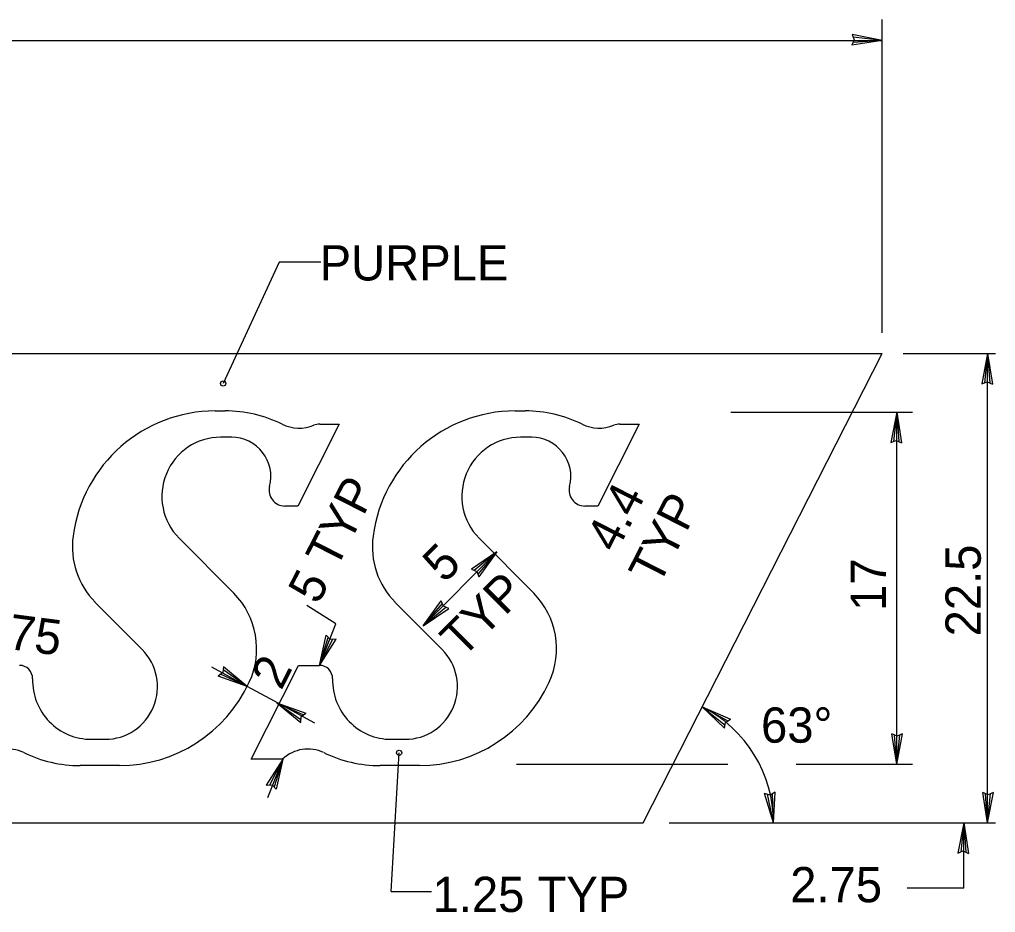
# Model space of a CAD drawing. Extents: x 10268197 to 10269179, y 2141503 to 2142677.
# Drawn here: x 10268496.62 to 10268515.98, y 2142153.63 to 2142171.35 of the extents above; entities that cross this region are included whole.
import ezdxf

# ---------------------------------------------------------------- set-up
doc = ezdxf.new("R2010")
doc.units = 0
for name, color, linetype in [('1', 7, 'Continuous'), ('2', 7, 'Continuous'), ('21', 7, 'Continuous')]:
    doc.layers.add(name, color=color, linetype=linetype)

msp = doc.modelspace()

# ---------------------------------------------------------------- linework, layer by layer
at = {"layer": '1'}
for p, q in [((10268513.738, 2142165.135), (10268513.738, 2142171.353)), ((10268491.278, 2142170.939), (10268513.738, 2142170.939)), ((10268513.181, 2142170.949), (10268513.133, 2142170.843)), ((10268513.738, 2142170.939), (10268513.133, 2142170.843)), ((10268513.738, 2142170.939), (10268513.137, 2142171.056)), ((10268513.137, 2142171.056), (10268513.181, 2142170.949)), ((10268513.738, 2142170.939), (10268513.159, 2142170.899)), ((10268513.738, 2142170.939), (10268513.16, 2142171)), ((10268501.773, 2142166.536), (10268500.658, 2142164.128)), ((10268502.595, 2142166.536), (10268501.773, 2142166.536)), ((10268514.152, 2142164.721), (10268515.983, 2142164.721)), ((10268515.827, 2142164.721), (10268515.71, 2142164.119)), ((10268515.827, 2142164.721), (10268515.767, 2142164.142)), ((10268515.827, 2142155.405), (10268515.827, 2142164.721)), ((10268515.827, 2142164.721), (10268515.923, 2142164.115)), ((10268515.827, 2142164.721), (10268515.868, 2142164.142)), ((10268515.71, 2142164.119), (10268515.817, 2142164.164)), ((10268515.817, 2142164.164), (10268515.923, 2142164.115)), ((10268510.735, 2142163.557), (10268514.337, 2142163.557)), ((10268514.023, 2142163.557), (10268513.907, 2142162.955)), ((10268514.023, 2142163.557), (10268513.963, 2142162.978)), ((10268514.023, 2142156.569), (10268514.023, 2142163.557)), ((10268514.023, 2142163.557), (10268514.119, 2142162.951)), ((10268514.023, 2142163.557), (10268514.064, 2142162.977)), ((10268513.907, 2142162.955), (10268514.014, 2142162.999)), ((10268514.014, 2142162.999), (10268514.119, 2142162.951)), ((10268504.628, 2142159.32), (10268506.092, 2142160.784)), ((10268506.092, 2142160.784), (10268505.584, 2142160.44)), ((10268506.092, 2142160.784), (10268505.64, 2142160.417)), ((10268506.092, 2142160.784), (10268505.711, 2142160.345)), ((10268506.092, 2142160.784), (10268505.732, 2142160.288)), ((10268505.584, 2142160.44), (10268505.691, 2142160.396)), ((10268505.691, 2142160.396), (10268505.732, 2142160.288)), ((10268502.894, 2142159.357), (10268502.319, 2142159.723)), ((10268504.628, 2142159.32), (10268504.988, 2142159.816)), ((10268504.628, 2142159.32), (10268505.01, 2142159.758)), ((10268504.628, 2142159.32), (10268505.08, 2142159.686)), ((10268505.029, 2142159.707), (10268504.988, 2142159.816)), ((10268505.137, 2142159.663), (10268505.029, 2142159.707)), ((10268504.628, 2142159.32), (10268505.137, 2142159.663)), ((10268502.571, 2142158.533), (10268502.894, 2142159.357)), ((10268502.571, 2142158.533), (10268502.703, 2142159.131)), ((10268502.783, 2142159.048), (10268502.703, 2142159.131)), ((10268502.571, 2142158.533), (10268502.744, 2142159.087)), ((10268502.571, 2142158.533), (10268502.899, 2142159.05)), ((10268502.571, 2142158.533), (10268502.838, 2142159.05)), ((10268502.899, 2142159.05), (10268502.783, 2142159.048)), ((10268501.138, 2142158.113), (10268500.438, 2142158.495)), ((10268501.592, 2142157.866), (10268501.138, 2142158.113)), ((10268502.479, 2142157.383), (10268501.592, 2142157.866)), ((10268510.166, 2142157.711), (10268510.726, 2142157.462)), ((10268510.166, 2142157.711), (10268510.608, 2142157.285)), ((10268510.166, 2142157.711), (10268510.618, 2142157.345)), ((10268510.166, 2142157.711), (10268510.674, 2142157.429)), ((10268510.608, 2142157.285), (10268510.628, 2142157.399)), ((10268510.628, 2142157.399), (10268510.726, 2142157.462)), ((10268514.023, 2142156.569), (10268513.927, 2142157.175)), ((10268514.033, 2142157.127), (10268513.927, 2142157.175)), ((10268514.023, 2142156.569), (10268514.14, 2142157.171)), ((10268514.14, 2142157.171), (10268514.033, 2142157.127)), ((10268514.023, 2142156.569), (10268513.983, 2142157.149)), ((10268514.023, 2142156.569), (10268514.084, 2142157.148)), ((10268503.991, 2142154.044), (10268504.15, 2142156.797)), ((10268501.844, 2142156.674), (10268501.516, 2142156.157)), ((10268501.844, 2142156.674), (10268501.541, 2142155.903)), ((10268501.844, 2142156.674), (10268501.577, 2142156.158)), ((10268501.844, 2142156.674), (10268501.67, 2142156.12)), ((10268501.844, 2142156.674), (10268501.713, 2142156.075)), ((10268506.478, 2142156.569), (10268510.674, 2142156.569)), ((10268512.027, 2142156.569), (10268514.337, 2142156.569)), ((10268501.516, 2142156.157), (10268501.632, 2142156.159)), ((10268501.632, 2142156.159), (10268501.713, 2142156.075)), ((10268511.612, 2142156.017), (10268511.512, 2142155.959)), ((10268511.579, 2142155.405), (10268511.612, 2142156.017)), ((10268515.827, 2142155.405), (10268515.731, 2142156.01)), ((10268515.836, 2142155.962), (10268515.731, 2142156.01)), ((10268515.827, 2142155.405), (10268515.944, 2142156.007)), ((10268515.944, 2142156.007), (10268515.836, 2142155.962)), ((10268511.579, 2142155.405), (10268511.4, 2142155.992)), ((10268511.512, 2142155.959), (10268511.4, 2142155.992)), ((10268511.579, 2142155.405), (10268511.458, 2142155.974)), ((10268511.579, 2142155.405), (10268511.559, 2142155.987)), ((10268515.827, 2142155.405), (10268515.786, 2142155.985)), ((10268515.827, 2142155.405), (10268515.887, 2142155.984)), ((10268509.509, 2142155.405), (10268515.983, 2142155.405)), ((10268515.355, 2142155.405), (10268515.239, 2142154.804)), ((10268515.355, 2142155.405), (10268515.295, 2142154.827)), ((10268515.355, 2142154.111), (10268515.355, 2142155.405)), ((10268515.355, 2142155.405), (10268515.451, 2142154.8)), ((10268515.355, 2142155.405), (10268515.396, 2142154.826)), ((10268515.239, 2142154.804), (10268515.345, 2142154.848)), ((10268515.345, 2142154.848), (10268515.451, 2142154.8)), ((10268515.355, 2142154.111), (10268514.23, 2142154.111)), ((10268503.991, 2142154.044), (10268504.795, 2142154.044))]:
    msp.add_line(p, q, dxfattribs=at)
for centre in [(10268500.658, 2142164.128), (10268504.15, 2142156.798)]:
    msp.add_circle(centre, 0.0518, dxfattribs=at)
msp.add_arc((10268508.992, 2142155.405), 2.588, 0, 63.0012, dxfattribs=at)
at = {"layer": '2'}
for p, q in [((10268484.215, 2142164.721), (10268513.738, 2142164.721)), ((10268508.992, 2142155.405), (10268513.738, 2142164.721)), ((10268500.503, 2142163.583), (10268500.699, 2142163.583)), ((10268506.454, 2142163.583), (10268506.651, 2142163.583)), ((10268502.964, 2142163.322), (10268502.142, 2142161.696)), ((10268502.576, 2142163.322), (10268502.964, 2142163.322)), ((10268508.916, 2142163.322), (10268508.094, 2142161.696)), ((10268508.528, 2142163.322), (10268508.916, 2142163.322)), ((10268500.83, 2142163.061), (10268500.608, 2142163.061)), ((10268506.782, 2142163.061), (10268506.559, 2142163.061)), ((10268502.142, 2142161.696), (10268501.883, 2142161.696)), ((10268508.094, 2142161.696), (10268507.835, 2142161.696)), ((10268499.785, 2142161.058), (10268500.87, 2142159.966)), ((10268505.736, 2142161.058), (10268506.821, 2142159.966)), ((10268499.054, 2142158.845), (10268498.122, 2142159.783)), ((10268505.005, 2142158.845), (10268504.074, 2142159.783)), ((10268501.216, 2142156.674), (10268502.156, 2142158.533)), ((10268502.156, 2142158.533), (10268502.571, 2142158.533)), ((10268498.042, 2142157.065), (10268498.322, 2142157.065)), ((10268503.994, 2142157.065), (10268504.273, 2142157.065)), ((10268501.844, 2142156.674), (10268501.216, 2142156.674)), ((10268498.6, 2142156.544), (10268497.821, 2142156.544)), ((10268504.552, 2142156.544), (10268503.773, 2142156.544)), ((10268483.351, 2142155.405), (10268508.992, 2142155.405))]:
    msp.add_line(p, q, dxfattribs=at)
for centre, major_axis, start_param, end_param in [((10268500.502, 2142160.715), (0, 2.868), 0, 1.436562), ((10268500.699, 2142160.976), (0, 2.607), 5.830963, 6.283185), ((10268506.454, 2142160.715), (0, 2.868), 0, 1.436562), ((10268506.65, 2142160.976), (0, 2.607), 5.830963, 6.283185), ((10268502.169, 2142164.024), (0, 0.782), 2.68937, 3.526171), ((10268502.576, 2142163.009), (0, 0.313), 0, 0.384579), ((10268508.12, 2142164.024), (0, 0.782), 2.68937, 3.526171), ((10268508.528, 2142163.009), (0, 0.313), 0, 0.384579), ((10268500.608, 2142161.888), (0, -1.173), 3.141593, 5.497787), ((10268500.83, 2142162.279), (0, -0.782), 1.321066, 3.141593), ((10268506.56, 2142161.888), (0, -1.173), 3.141593, 5.497787), ((10268506.782, 2142162.279), (0, -0.782), 1.321066, 3.141593), ((10268501.883, 2142162.009), (0, -0.313), 4.462658, 6.283185), ((10268507.835, 2142162.009), (0, -0.313), 4.462658, 6.283185), ((10268499.22, 2142160.89), (0, 1.564), 1.436562, 2.356194), ((10268505.172, 2142160.89), (0, 1.564), 1.436562, 2.356194), ((10268499.772, 2142158.86), (0, -1.564), 1.133591, 2.356194), ((10268505.723, 2142158.86), (0, -1.564), 1.133591, 2.356194), ((10268498.321, 2142158.108), (0, -1.043), 0, 2.356194), ((10268504.273, 2142158.108), (0, -1.043), 0, 2.356194), ((10268496.619, 2142158.272), (0, 0.261), 4.689114, 6.283185), ((10268502.571, 2142158.272), (0, 0.261), 4.689114, 6.283185), ((10268498.042, 2142158.238), (0, 1.173), 1.547521, 3.141593), ((10268498.599, 2142159.412), (0, -2.868), 0, 1.133591), ((10268503.994, 2142158.238), (0, 1.173), 1.547521, 3.141593), ((10268504.551, 2142159.412), (0, -2.868), 0, 1.133591), ((10268496.389, 2142156.142), (0, -0.73), 2.69443, 3.895387), ((10268497.821, 2142159.151), (0, -2.607), 5.836023, 6.283185), ((10268502.34, 2142156.142), (0, -0.73), 2.69443, 3.895387), ((10268503.773, 2142159.151), (0, -2.607), 5.836023, 6.283185)]:
    msp.add_ellipse(centre, major_axis=major_axis, ratio=0.992614, start_param=start_param, end_param=end_param, dxfattribs=at)
at = {"layer": '21'}
for p, q in [((10268500.652, 2142158.389), (10268500.56, 2142158.319)), ((10268501.138, 2142158.113), (10268500.609, 2142158.356)), ((10268500.665, 2142158.505), (10268500.652, 2142158.389)), ((10268501.138, 2142158.113), (10268500.658, 2142158.444)), ((10268501.138, 2142158.113), (10268500.665, 2142158.505)), ((10268501.138, 2142158.113), (10268500.56, 2142158.319)), ((10268501.724, 2142157.79), (10268502.303, 2142157.585)), ((10268501.724, 2142157.79), (10268502.198, 2142157.399)), ((10268501.724, 2142157.79), (10268502.204, 2142157.46)), ((10268501.724, 2142157.79), (10268502.254, 2142157.548)), ((10268502.21, 2142157.515), (10268502.303, 2142157.585)), ((10268502.198, 2142157.399), (10268502.21, 2142157.515))]:
    msp.add_line(p, q, dxfattribs=at)

# ---------------------------------------------------------------- texts
at = {"layer": '1'}
for s, p in [('PURPLE', (10268502.574, 2142166.173)), ('63°', (10268511.332, 2142156.998)), ('2.75', (10268511.911, 2142153.83)), ('1.25 TYP', (10268504.815, 2142153.637))]:
    msp.add_text(s, height=0.7, dxfattribs=at).set_placement(p)
for s, rotation, p in [('5 TYP', 62.9994, (10268502.544, 2142159.719)), ('4.4', 63, (10268508.458, 2142160.743)), ('TYP', 63, (10268509.304, 2142160.091)), ('5', 45, (10268505.05, 2142160.147)), ('22.5', 90, (10268515.691, 2142159.108)), ('17', 90, (10268513.811, 2142159.614)), ('TYP', 45, (10268505.403, 2142158.657)), ('3.75', 352.5994, (10268495.597, 2142158.961)), ('2', 63, (10268501.812, 2142158.02))]:
    msp.add_text(s, height=0.7, rotation=rotation, dxfattribs=at).set_placement(p)

doc.saveas('drawing.dxf')
